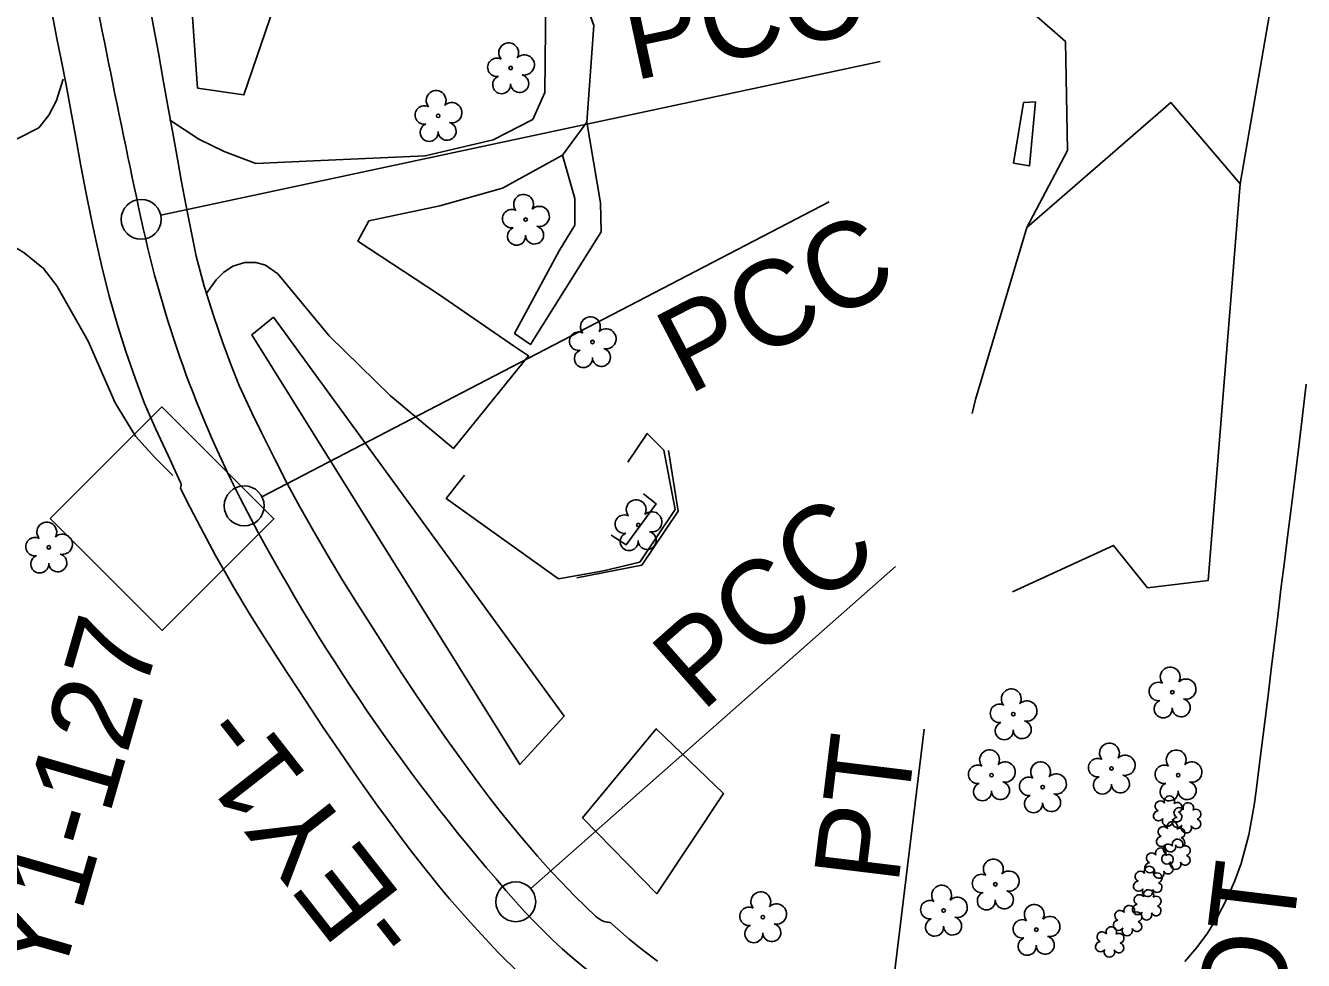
# Model space of a CAD drawing. Extents: x 479429 to 482809, y 488118 to 492379.
# Drawn here: x 481121.6 to 481361.5, y 490861 to 491036.5 of the extents above; entities that cross this region are included whole.
import ezdxf

# ---------------------------------------------------------------- set-up
doc = ezdxf.new("R2010")
doc.units = 0
for name, color, linetype in [('CTL Secondary Horizontal and Vertical CELL', 7, 'Continuous'), ('CTL Secondary Horizontal and Vertical Text', 7, 'Continuous'), ('Exist Horizontal Alignment', 7, 'Continuous'), ('Exist Horizontal Alignment Direction Label', 7, 'Continuous'), ('Exist Other Culture Area Outline', 7, 'Continuous'), ('Exist Other Culture Fence Line', 7, 'Continuous'), ('Exist Roads EOP', 7, 'Continuous'), ('Exist Roads EOP Other', 7, 'Continuous'), ('Exist Vegetation Hedge Row', 7, 'Continuous'), ('Exist Vegetation Shrub CELL', 7, 'Continuous'), ('Exist Vegetation Tree CELL', 7, 'Continuous'), ('Exist Vegetation Woods Line', 7, 'Continuous')]:
    doc.layers.add(name, color=color, linetype=linetype)

msp = doc.modelspace()

# ---------------------------------------------------------------- linework, layer by layer
at = {"layer": 'CTL Secondary Horizontal and Vertical CELL'}
msp.add_line((481147.06, 490943.89), (481147.06, 490943.89), dxfattribs=at)
msp.add_lwpolyline([(481126.2, 490943.96), (481147.17, 490964.93), (481168.17, 490943.92), (481147.21, 490922.96)], close=True, dxfattribs=at)
at = {"layer": 'Exist Horizontal Alignment'}
for p, q in [((481146.93, 491000.92), (481281.99, 491029.79)), ((481165.93, 490948.07), (481272.42, 491003.44)), ((481216.4, 490874.5), (481284.9, 490934.98)), ((481282.37, 490839.78), (481290.26, 490904.44))]:
    msp.add_line(p, q, dxfattribs=at)
for centre in [(481143.26, 491000.14), (481162.6, 490946.34), (481213.59, 490872.02)]:
    msp.add_circle(centre, 3.75, dxfattribs=at)
for centre, radius, start, end in [((483795.69, 491567.07), 2712.34, 190.71117, 192.06493), ((481351.79, 491044.71), 213.23, 192.0649, 207.472), ((481491.46, 491117.33), 370.65, 207.472, 221.4386), ((481295.08, 490943.97), 108.71, 221.4386, 263.0452)]:
    msp.add_arc(centre, radius, start, end, dxfattribs=at)
at = {"layer": 'Exist Other Culture Area Outline'}
for points in [[(481226.92, 491018.4), (481229.51, 491003.22), (481229.64, 490997.78), (481216.35, 490976.63), (481213.36, 490978.73), (481221.76, 490994.23), (481224.66, 490999.06), (481224.68, 491004.03), (481222.36, 491012.21)], [(481234.66, 490954.57), (481238.25, 490959.96), (481241.42, 490956.79), (481243.55, 490945.66), (481236.86, 490935.77), (481230.07, 490934.13)], [(481230.07, 490934.13), (481221.59, 490932.67), (481200.55, 490947.72), (481203.97, 490952.11)], [(481231.53, 490940.82), (481234.34, 490939.04), (481239.96, 490946.71), (481237.55, 490948.58)]]:
    msp.add_lwpolyline(points, dxfattribs=at)
at = {"layer": 'Exist Other Culture Fence Line'}
msp.add_lwpolyline([(481225.05, 490932.84), (481237.24, 490935.2), (481244.09, 490945.34), (481242.25, 490956.73)], dxfattribs=at)
at = {"layer": 'Exist Roads EOP'}
for points in [[(481214.28, 490858.58), (481210.26, 490862.5), (481207.13, 490865.85), (481205.07, 490868.14), (481201.18, 490872.57), (481199.27, 490874.85), (481196.82, 490877.9), (481194.23, 490881.21), (481191.89, 490884.29), (481189.68, 490887.25), (481187.52, 490890.22), (481185.37, 490893.23), (481183.19, 490896.34), (481179.81, 490901.27), (481177.46, 490904.74), (481175.16, 490908.19), (481172.91, 490911.6), (481170.63, 490915.11), (481168.31, 490918.71), (481166, 490922.32), (481163.75, 490925.9), (481160.66, 490931.02), (481158.84, 490934.18), (481157.24, 490937.05), (481154.4, 490942.32), (481151.78, 490947.33), (481150.63, 490949.68), (481150.77, 490950.25), (481150.75, 490950.48), (481150.67, 490950.74), (481148.31, 490955.8), (481145.93, 490960.86), (481143.9, 490965.54), (481142.11, 490970.29), (481140.47, 490975.14), (481138.9, 490980.07), (481137.26, 490985.74), (481135.83, 490991.53), (481134.82, 490995.95), (481133.87, 491000.33), (481132.93, 491004.98), (481131.95, 491010.17), (481130.98, 491015.5), (481130.07, 491020.58), (481129.19, 491025.38), (481128.31, 491029.85), (481127.45, 491034.06), (481127.05, 491036.1), (481126.28, 491040.02)], [(481144.75, 491040.86), (481145.59, 491036.37), (481146.49, 491031.4), (481147.41, 491026.27), (481148.34, 491021.07), (481149.26, 491015.97), (481150.13, 491011.14), (481150.79, 491007.5), (481151.71, 491002.58), (481152.69, 490997.58), (481153.61, 490993.22), (481155.09, 490987.59), (481156.88, 490981.87), (481158.57, 490976.94), (481160.22, 490972.55), (481161.66, 490968.96), (481164.1, 490963.7), (481165.88, 490960.09), (481168.43, 490955.01), (481170.75, 490950.44), (481173.04, 490946.17), (481175.66, 490941.56), (481178.38, 490936.93), (481181.09, 490932.39), (481183.8, 490928.03), (481186.81, 490923.3), (481189.91, 490918.5), (481192.23, 490914.85), (481194.94, 490910.77), (481196.58, 490908.35), (481198.38, 490905.74), (481200.34, 490902.94), (481202.44, 490899.98), (481204.57, 490897.05), (481206.69, 490894.2), (481208.75, 490891.47), (481210.74, 490888.87), (481214.39, 490884.37), (481217.7, 490880.58), (481220.2, 490877.77), (481222.1, 490875.74), (481224.67, 490873.05), (481228.7, 490869.19), (481229.61, 490868.56), (481229.89, 490868.41), (481230.16, 490868.31), (481230.44, 490868.23), (481230.77, 490868.19), (481230.97, 490868.19), (481231.18, 490868.14), (481231.43, 490868.03), (481231.7, 490867.83), (481234.91, 490864.99), (481237.36, 490863.01), (481240.21, 490860.89)], [(481339.23, 490860.83), (481341.48, 490863.41), (481343.44, 490866.11), (481345.32, 490869.16), (481346.97, 490872.29), (481348.51, 490875.79), (481349.79, 490879.23), (481351.25, 490884.59), (481352.21, 490890.13), (481352.6, 490892.86), (481353.07, 490896.45), (481353.64, 490900.91), (481354.24, 490905.81), (481354.85, 490910.73), (481355.45, 490915.67), (481356.05, 490920.63), (481356.65, 490925.63), (481357.27, 490930.7), (481357.91, 490935.84), (481358.56, 490941.04), (481359.23, 490946.36), (481359.92, 490951.84), (481360.61, 490957.5), (481361.31, 490963.33), (481362.02, 490969.22)]]:
    msp.add_lwpolyline(points, dxfattribs=at)
at = {"layer": 'Exist Roads EOP Other'}
for points in [[(481224.96, 491045.86), (481228.26, 491036.52)], [(481209.35, 491015.06), (481216.77, 491018.91), (481219.04, 491023.93), (481219.21, 491041.83)], [(481211.13, 491006.01), (481222.36, 491012.21), (481226.92, 491018.4), (481228.26, 491036.52)], [(481054.34, 490997.22), (481057.87, 490999.28), (481061.71, 491001.13), (481067.32, 491003.23), (481073.64, 491005.42), (481078.33, 491006.84), (481084.04, 491007.88), (481088.9, 491008.51), (481095.04, 491009.09), (481101.93, 491010.32), (481107.91, 491011.53), (481114.89, 491013.32), (481120.11, 491015.29), (481124.02, 491017.3), (481125.95, 491019.67), (481127.35, 491022.46), (481127.62, 491023.23), (481128.62, 491026.47)], [(481148.58, 491018.83), (481154.11, 491015.2), (481158.86, 491012.88), (481164.8, 491010.63), (481175.63, 491011.13), (481196.59, 491012.03), (481209.35, 491015.06)], [(481211.13, 491006.01), (481199.34, 491002.68), (481186.02, 490999.86), (481183.96, 490996.04), (481199.09, 490986.07), (481213.33, 490976.25), (481216.01, 490974.53), (481201.88, 490957.14), (481190.1, 490966.98), (481178.56, 490978.27), (481168.91, 490989.9), (481166.63, 490991.56), (481164.77, 490992.01), (481162.7, 490992.01), (481160.44, 490991.33), (481158.71, 490990.16), (481157.32, 490988.77), (481155.61, 490986.31)], [(481149.23, 490952.04), (481145.81, 490955.42), (481142.2, 490959.44), (481138.39, 490965.71), (481133.32, 490977.24), (481127.4, 490987.65), (481124.91, 490990.93), (481121.32, 490993.83), (481116.71, 490996.59), (481114.03, 490997.59), (481111.68, 490998.3), (481106.61, 490999.24), (481099.92, 490999.38), (481087.46, 490998.88), (481080.89, 490997.59), (481074.58, 490995.84), (481068.34, 490993.5), (481060.39, 490989.91), (481056.37, 490987.51)]]:
    msp.add_lwpolyline(points, dxfattribs=at)
at = {"layer": 'Exist Vegetation Hedge Row'}
msp.add_line((481358.47, 491058.43), (481349.63, 491006.82), dxfattribs=at)
for points in [[(481309.55, 490998.59), (481317.17, 491013.08), (481316.79, 491033.53), (481305.4, 491043.54), (481299.28, 491050.19), (481290.94, 491053.61), (481290.73, 491057.43), (481298.3, 491063.81)], [(481311.2, 491022.2), (481310.02, 491010.16), (481307.06, 491010.71), (481308.93, 491022.07), (481311.2, 491022.2)]]:
    msp.add_lwpolyline(points, dxfattribs=at)
at = {"layer": 'Exist Vegetation Shrub CELL'}
for p, q in [((481336.09, 490888.86), (481336.09, 490888.86)), ((481339.63, 490887.59), (481339.63, 490887.59)), ((481336.64, 490884.04), (481336.64, 490884.04)), ((481337.63, 490880.75), (481337.63, 490880.75)), ((481334.46, 490879.1), (481334.46, 490879.1)), ((481332.34, 490875.64), (481332.34, 490875.64)), ((481332.15, 490871.25), (481332.15, 490871.25)), ((481328.54, 490868.3), (481328.54, 490868.3)), ((481325.19, 490864.29), (481325.19, 490864.29))]:
    msp.add_line(p, q, dxfattribs=at)
for centre, radius, start, end in [((481334.61, 490889.99), 0.968, 35.8908, 245.4216), ((481336.32, 490890.9), 0.99, 334.8391, 200.4717), ((481337.77, 490889.73), 0.929, 284.4567, 126.0861), ((481339.86, 490889.63), 0.99, 334.8391, 200.4717), ((481334.29, 490888.16), 0.955, 95.1099, 327.9534), ((481335.97, 490887.18), 0.984, 151.2797, 21.387), ((481337.83, 490886.89), 0.955, 95.1099, 327.9534), ((481337.73, 490887.93), 0.937, 204.9913, 73.4601), ((481338.14, 490888.72), 0.968, 35.8908, 245.4216), ((481341.26, 490886.66), 0.937, 204.9913, 73.4601), ((481341.3, 490888.46), 0.929, 284.4567, 126.0861), ((481335.16, 490885.17), 0.968, 35.8908, 245.4216), ((481336.87, 490886.08), 0.99, 334.8391, 200.4717), ((481338.32, 490884.91), 0.929, 284.4567, 126.0861), ((481339.5, 490885.91), 0.984, 151.2797, 21.387), ((481334.84, 490883.34), 0.955, 95.1099, 327.9534), ((481336.14, 490881.88), 0.968, 35.8908, 245.4216), ((481336.52, 490882.36), 0.984, 151.2797, 21.387), ((481337.85, 490882.79), 0.99, 334.8391, 200.4717), ((481338.28, 490883.11), 0.937, 204.9913, 73.4601), ((481332.97, 490880.23), 0.968, 35.8908, 245.4216), ((481334.69, 490881.14), 0.99, 334.8391, 200.4717), ((481335.83, 490880.05), 0.955, 95.1099, 327.9534), ((481336.13, 490879.97), 0.929, 284.4567, 126.0861), ((481339.26, 490879.82), 0.937, 204.9913, 73.4601), ((481339.3, 490881.62), 0.929, 284.4567, 126.0861), ((481332.57, 490877.68), 0.99, 334.8391, 200.4717), ((481332.66, 490878.4), 0.955, 95.1099, 327.9534), ((481334.33, 490877.42), 0.984, 151.2797, 21.387), ((481336.09, 490878.17), 0.937, 204.9913, 73.4601), ((481337.5, 490879.07), 0.984, 151.2797, 21.387), ((481330.54, 490874.94), 0.955, 95.1099, 327.9534), ((481330.86, 490876.77), 0.968, 35.8908, 245.4216), ((481333.98, 490874.71), 0.937, 204.9913, 73.4601), ((481334.02, 490876.51), 0.929, 284.4567, 126.0861), ((481330.67, 490872.38), 0.968, 35.8908, 245.4216), ((481332.22, 490873.96), 0.984, 151.2797, 21.387), ((481332.38, 490873.29), 0.99, 334.8391, 200.4717), ((481333.83, 490872.12), 0.929, 284.4567, 126.0861), ((481328.77, 490870.34), 0.99, 334.8391, 200.4717), ((481330.35, 490870.55), 0.955, 95.1099, 327.9534), ((481333.79, 490870.32), 0.937, 204.9913, 73.4601), ((481326.74, 490867.6), 0.955, 95.1099, 327.9534), ((481327.06, 490869.43), 0.968, 35.8908, 245.4216), ((481330.18, 490867.37), 0.937, 204.9913, 73.4601), ((481330.21, 490869.17), 0.929, 284.4567, 126.0861), ((481332.03, 490869.57), 0.984, 151.2797, 21.387), ((481323.7, 490865.42), 0.968, 35.8908, 245.4216), ((481325.42, 490866.34), 0.99, 334.8391, 200.4717), ((481326.86, 490865.16), 0.929, 284.4567, 126.0861), ((481328.41, 490866.62), 0.984, 151.2797, 21.387), ((481323.39, 490863.59), 0.955, 95.1099, 327.9534), ((481326.82, 490863.37), 0.937, 204.9913, 73.4601), ((481325.06, 490862.61), 0.984, 151.2797, 21.387)]:
    msp.add_arc(centre, radius, start, end, dxfattribs=at)
at = {"layer": 'Exist Vegetation Tree CELL'}
for p, q in [((481212.64, 491028.54), (481212.64, 491028.54)), ((481199.03, 491019.57), (481199.03, 491019.57)), ((481215.45, 491000.09), (481215.45, 491000.09)), ((481227.99, 490977.11), (481227.99, 490977.11)), ((481236.59, 490942.75), (481236.59, 490942.75)), ((481125.92, 490938.55), (481125.92, 490938.55)), ((481336.86, 490911.35), (481336.86, 490911.35)), ((481307.01, 490907.24), (481307.01, 490907.24)), ((481325.45, 490897.05), (481325.45, 490897.05)), ((481302.92, 490895.79), (481302.92, 490895.79)), ((481337.98, 490895.78), (481337.98, 490895.78)), ((481312.52, 490893.54), (481312.52, 490893.54)), ((481303.64, 490875.3), (481303.64, 490875.3)), ((481259.99, 490869.13), (481259.99, 490869.13)), ((481293.93, 490870.37), (481293.93, 490870.37)), ((481311.32, 490866.78), (481311.32, 490866.78))]:
    msp.add_line(p, q, dxfattribs=at)
for centre in [(481212.64, 491028.54), (481199.03, 491019.57), (481215.45, 491000.09), (481227.99, 490977.11), (481236.59, 490942.75), (481125.92, 490938.55), (481336.86, 490911.35), (481307.01, 490907.24), (481325.45, 490897.05), (481302.92, 490895.79), (481337.98, 490895.78), (481312.52, 490893.54), (481303.64, 490875.3), (481293.93, 490870.37), (481259.99, 490869.13), (481311.32, 490866.78)]:
    msp.add_circle(centre, 0.326, dxfattribs=at)
for centre, radius, start, end in [((481212.26, 491031.41), 1.86, 330.1651, 219.7134), ((481210.04, 491028.69), 1.73, 62.6636, 279.3457), ((481215.19, 491029.13), 1.9, 257.1011, 134.1999), ((481210.94, 491025.42), 1.69, 111.5671, 6.231), ((481214.32, 491025.64), 1.7, 181.2822, 74.56), ((481198.64, 491022.45), 1.86, 330.1651, 219.7134), ((481201.58, 491020.16), 1.9, 257.1011, 134.1999), ((481196.42, 491019.73), 1.73, 62.6636, 279.3457), ((481197.32, 491016.45), 1.69, 111.5671, 6.231), ((481200.7, 491016.67), 1.7, 181.2822, 74.56), ((481215.06, 491002.97), 1.86, 330.1651, 219.7134), ((481212.84, 491000.25), 1.73, 62.6636, 279.3457), ((481218, 491000.68), 1.9, 257.1011, 134.1999), ((481213.74, 490996.97), 1.69, 111.5671, 6.231), ((481217.12, 490997.2), 1.7, 181.2822, 74.56), ((481227.61, 490979.98), 1.86, 330.1651, 219.7134), ((481225.39, 490977.26), 1.73, 62.6636, 279.3457), ((481230.54, 490977.7), 1.9, 257.1011, 134.1999), ((481226.29, 490973.99), 1.69, 111.5671, 6.231), ((481229.67, 490974.21), 1.7, 181.2822, 74.56), ((481236.2, 490945.63), 1.86, 330.1651, 219.7134), ((481239.14, 490943.34), 1.9, 257.1011, 134.1999), ((481125.54, 490941.42), 1.86, 330.1651, 219.7134), ((481233.98, 490942.91), 1.73, 62.6636, 279.3457), ((481123.32, 490938.7), 1.73, 62.6636, 279.3457), ((481128.47, 490939.14), 1.9, 257.1011, 134.1999), ((481234.88, 490939.63), 1.69, 111.5671, 6.231), ((481238.26, 490939.86), 1.7, 181.2822, 74.56), ((481124.22, 490935.43), 1.69, 111.5671, 6.231), ((481127.6, 490935.65), 1.7, 181.2822, 74.56), ((481336.47, 490914.22), 1.86, 330.1651, 219.7134), ((481339.41, 490911.94), 1.9, 257.1011, 134.1999), ((481306.63, 490910.11), 1.86, 330.1651, 219.7134), ((481334.25, 490911.5), 1.73, 62.6636, 279.3457), ((481304.41, 490907.39), 1.73, 62.6636, 279.3457), ((481309.56, 490907.83), 1.9, 257.1011, 134.1999), ((481335.15, 490908.23), 1.69, 111.5671, 6.231), ((481338.53, 490908.45), 1.7, 181.2822, 74.56), ((481305.31, 490904.12), 1.69, 111.5671, 6.231), ((481308.68, 490904.34), 1.7, 181.2822, 74.56), ((481302.54, 490898.66), 1.86, 330.1651, 219.7134), ((481325.06, 490899.93), 1.86, 330.1651, 219.7134), ((481327.99, 490897.64), 1.9, 257.1011, 134.1999), ((481337.59, 490898.65), 1.86, 330.1651, 219.7134), ((481300.32, 490895.94), 1.73, 62.6636, 279.3457), ((481305.47, 490896.38), 1.9, 257.1011, 134.1999), ((481312.13, 490896.42), 1.86, 330.1651, 219.7134), ((481322.84, 490897.21), 1.73, 62.6636, 279.3457), ((481335.37, 490895.93), 1.73, 62.6636, 279.3457), ((481340.52, 490896.37), 1.9, 257.1011, 134.1999), ((481309.91, 490893.7), 1.73, 62.6636, 279.3457), ((481315.07, 490894.13), 1.9, 257.1011, 134.1999), ((481323.74, 490893.93), 1.69, 111.5671, 6.231), ((481327.12, 490894.15), 1.7, 181.2822, 74.56), ((481301.22, 490892.67), 1.69, 111.5671, 6.231), ((481304.6, 490892.89), 1.7, 181.2822, 74.56), ((481314.19, 490890.64), 1.7, 181.2822, 74.56), ((481336.27, 490892.66), 1.69, 111.5671, 6.231), ((481339.65, 490892.88), 1.7, 181.2822, 74.56), ((481310.81, 490890.42), 1.69, 111.5671, 6.231), ((481303.26, 490878.17), 1.86, 330.1651, 219.7134), ((481301.04, 490875.45), 1.73, 62.6636, 279.3457), ((481306.19, 490875.89), 1.9, 257.1011, 134.1999), ((481259.6, 490872.01), 1.86, 330.1651, 219.7134), ((481293.55, 490873.25), 1.86, 330.1651, 219.7134), ((481301.94, 490872.18), 1.69, 111.5671, 6.231), ((481305.32, 490872.4), 1.7, 181.2822, 74.56), ((481257.38, 490869.29), 1.73, 62.6636, 279.3457), ((481262.54, 490869.72), 1.9, 257.1011, 134.1999), ((481291.33, 490870.53), 1.73, 62.6636, 279.3457), ((481296.48, 490870.96), 1.9, 257.1011, 134.1999), ((481310.94, 490869.65), 1.86, 330.1651, 219.7134), ((481292.23, 490867.25), 1.69, 111.5671, 6.231), ((481295.61, 490867.47), 1.7, 181.2822, 74.56), ((481308.72, 490866.93), 1.73, 62.6636, 279.3457), ((481313.87, 490867.37), 1.9, 257.1011, 134.1999), ((481258.28, 490866.01), 1.69, 111.5671, 6.231), ((481261.66, 490866.23), 1.7, 181.2822, 74.56), ((481309.62, 490863.66), 1.69, 111.5671, 6.231), ((481313, 490863.88), 1.7, 181.2822, 74.56)]:
    msp.add_arc(centre, radius, start, end, dxfattribs=at)
at = {"layer": 'Exist Vegetation Woods Line'}
for points in [[(481149.44, 491087.31), (481186.39, 491086.83), (481179.45, 491072.97), (481162.56, 491023.49), (481153.86, 491024.79), (481149.44, 491087.31)], [(481299.29, 490963.66), (481299.92, 490966.33), (481309.55, 490998.59), (481336.61, 491022.06), (481349.63, 491006.82), (481343.58, 490932.3), (481332.21, 490930.94), (481325.8, 490938.93), (481306.86, 490930.19)], [(481168.11, 490981.78), (481222.67, 490906.87), (481214.35, 490897.81), (481164.01, 490978.45), (481168.11, 490981.78)], [(481226.13, 490887.75), (481239.97, 490904.51), (481252.58, 490892.34), (481240.05, 490873.51), (481226.13, 490887.75)]]:
    msp.add_lwpolyline(points, dxfattribs=at)

# ---------------------------------------------------------------- texts
at = {"layer": 'CTL Secondary Horizontal and Vertical Text'}
msp.add_text('BY1-127', height=16, rotation=73.904, dxfattribs=at).set_placement((481124.08, 490842.35))
at = {"layer": 'Exist Horizontal Alignment'}
for s, rotation, p in [('PCC', 12.0649, (481235.76, 491026.15)), ('PCC', 27.472, (481245.97, 490967.06)), ('PCC', 41.4386, (481248.54, 490907.46)), ('PT', 83.0452, (481285.39, 490875.01)), ('POT', 83.0452, (481355.64, 490834.63))]:
    msp.add_text(s, height=16, rotation=rotation, dxfattribs=at).set_placement(p)
at = {"layer": 'Exist Horizontal Alignment Direction Label'}
msp.add_text('-EY1-', height=16, rotation=128.0598, dxfattribs=at).set_placement((481196.82, 490867.3))

doc.saveas('drawing.dxf')
